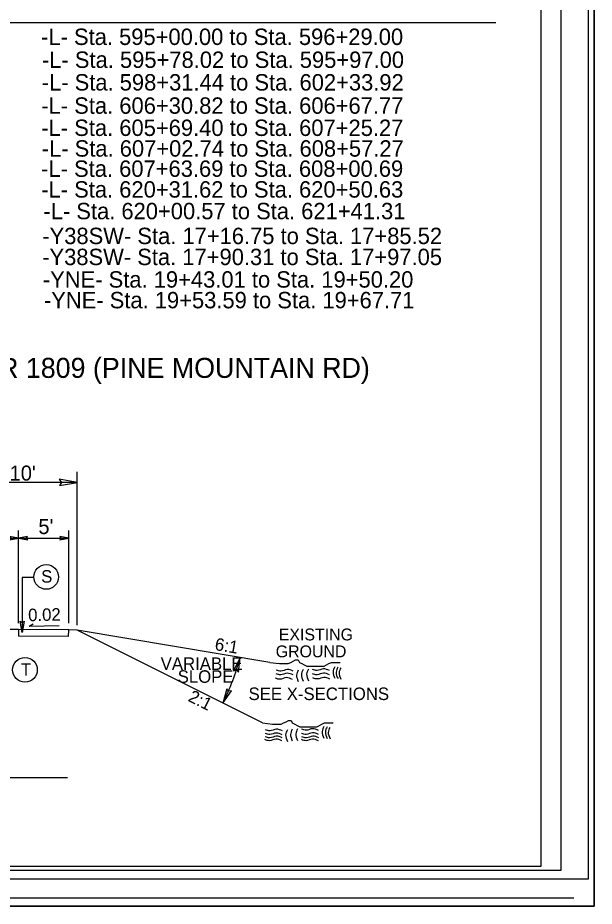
# Model space of a CAD drawing. Extents: x 2294455 to 2294795, y 719276 to 719941.
# Drawn here: x 2294722.6 to 2294794.5, y 719495.3 to 719606.2 of the extents above; entities that cross this region are included whole.
import ezdxf

# ---------------------------------------------------------------- set-up
doc = ezdxf.new("R2010")
doc.units = 0
for name, color, linetype in [('Default', 7, 'Continuous'), ('Old_Level_1', 7, 'Continuous'), ('Old_Level_11', 7, 'Continuous'), ('Old_Level_2', 7, 'Continuous'), ('Old_Level_3', 7, 'Continuous'), ('Sheet Cutting Line CELL', 7, 'Continuous'), ('Sheet Plot Border Inside CELL', 7, 'Continuous'), ('Sheet Plot Border Outside CELL', 7, 'Continuous'), ('Sheet Typical CELL', 7, 'Continuous'), ('Typical Hinge Slope Arterial CELL', 7, 'Continuous'), ('Typical ID Circle CELL', 7, 'Continuous'), ('Typical Terminator CELL', 7, 'Continuous'), ('Typical Text ID Circle CELL', 7, 'Continuous')]:
    doc.layers.add(name, color=color, linetype=linetype)

msp = doc.modelspace()

# ---------------------------------------------------------------- linework, layer by layer
at = {"layer": 'Default'}
msp.add_lwpolyline([(2294454.52, 719715.33), (2294794.52, 719715.33), (2294794.52, 719495.33), (2294454.52, 719495.33)], close=True, dxfattribs=at)
at = {"layer": 'Old_Level_1'}
for p, q in [((2294724.02, 719530.26), (2294724.53, 719530.57)), ((2294724.02, 719530.26), (2294727.79, 719530.34)), ((2294722.72, 719529.84), (2294717.54, 719529.88)), ((2294722.72, 719529.84), (2294722.71, 719529.01)), ((2294728.97, 719529.8), (2294722.72, 719529.84)), ((2294728.94, 719528.97), (2294728.97, 719529.8)), ((2294730.03, 719529.75), (2294728.97, 719529.8)), ((2294753.16, 719518.19), (2294730.03, 719529.75)), ((2294728.94, 719528.97), (2294722.71, 719529.01))]:
    msp.add_line(p, q, dxfattribs=at)
at = {"layer": 'Old_Level_11'}
for p, q in [((2294720.71, 719605.56), (2294782.24, 719605.56)), ((2294730.03, 719530.41), (2294730.03, 719549.52)), ((2294730.05, 719548.21), (2294714.42, 719548.21)), ((2294722.72, 719530.63), (2294722.72, 719542.19)), ((2294728.97, 719530.63), (2294728.97, 719542.19)), ((2294716.92, 719541.25), (2294728.97, 719541.25)), ((2294728.83, 719511.36), (2294666.82, 719511.36))]:
    msp.add_line(p, q, dxfattribs=at)
for points in [[(2294727.8, 719547.83), (2294730.05, 719548.21), (2294727.78, 719548.61), (2294728.07, 719548.21)], [(2294721.59, 719541.05), (2294722.72, 719541.25), (2294721.58, 719541.45), (2294721.73, 719541.25)], [(2294723.84, 719541.44), (2294722.72, 719541.25), (2294723.85, 719541.05), (2294723.7, 719541.25)], [(2294727.84, 719541.05), (2294728.97, 719541.25), (2294727.84, 719541.45), (2294727.98, 719541.25)], [(2294750.14, 719524.51), (2294750.34, 719526.37), (2294749.51, 719524.68), (2294749.89, 719524.82)], [(2294748.7, 719522.47), (2294748.21, 719520.67), (2294749.29, 719522.21), (2294748.89, 719522.14)]]:
    msp.add_lwpolyline(points, close=True, dxfattribs=at)
at = {"layer": 'Old_Level_2'}
for points in [[(2294756.98, 719524.65), (2294756.22, 719524.86), (2294755.43, 719524.66), (2294754.86, 719524.79)], [(2294756.98, 719524.65), (2294756.22, 719524.86), (2294755.43, 719524.66), (2294754.86, 719524.79)], [(2294757.6, 719524.79), (2294757.39, 719524.17), (2294757.61, 719523.35)], [(2294758.2, 719524.85), (2294757.99, 719524.22), (2294758.22, 719523.4)], [(2294758.2, 719524.85), (2294757.99, 719524.22), (2294758.22, 719523.4)], [(2294758.86, 719524.9), (2294758.65, 719524.28), (2294758.87, 719523.45)], [(2294758.86, 719524.9), (2294758.65, 719524.28), (2294758.87, 719523.45)], [(2294761.49, 719524.72), (2294760.74, 719524.94), (2294759.94, 719524.73), (2294759.37, 719524.86)], [(2294761.49, 719524.72), (2294760.74, 719524.94), (2294759.94, 719524.73), (2294759.37, 719524.86)], [(2294762.15, 719525.2), (2294761.94, 719524.58), (2294762.17, 719523.76)], [(2294762.15, 719525.2), (2294761.94, 719524.58), (2294762.17, 719523.76)], [(2294762.54, 719525.16), (2294762.33, 719524.54), (2294762.56, 719523.72)], [(2294762.54, 719525.16), (2294762.33, 719524.54), (2294762.56, 719523.72)], [(2294762.91, 719525.09), (2294762.7, 719524.47), (2294762.92, 719523.65)], [(2294762.91, 719525.09), (2294762.7, 719524.47), (2294762.92, 719523.65)], [(2294756.88, 719523.63), (2294756.13, 719523.85), (2294755.33, 719523.64), (2294754.76, 719523.77)], [(2294756.88, 719523.63), (2294756.13, 719523.85), (2294755.33, 719523.64), (2294754.76, 719523.77)], [(2294756.96, 719524.18), (2294756.2, 719524.39), (2294755.41, 719524.19), (2294754.84, 719524.32)], [(2294756.96, 719524.18), (2294756.2, 719524.39), (2294755.41, 719524.19), (2294754.84, 719524.32)], [(2294761.49, 719524.2), (2294760.74, 719524.41), (2294759.95, 719524.21), (2294759.38, 719524.34)], [(2294761.49, 719524.2), (2294760.74, 719524.41), (2294759.95, 719524.21), (2294759.38, 719524.34)], [(2294761.55, 719523.67), (2294760.8, 719523.88), (2294760, 719523.68), (2294759.43, 719523.81)], [(2294761.55, 719523.67), (2294760.8, 719523.88), (2294760, 719523.68), (2294759.43, 719523.81)], [(2294755.62, 719517.2), (2294754.87, 719517.41), (2294754.08, 719517.21), (2294753.5, 719517.34)], [(2294756.24, 719517.34), (2294756.03, 719516.72), (2294756.26, 719515.9)], [(2294756.24, 719517.34), (2294756.03, 719516.72), (2294756.26, 719515.9)], [(2294756.85, 719517.4), (2294756.64, 719516.77), (2294756.86, 719515.95)], [(2294756.85, 719517.4), (2294756.64, 719516.77), (2294756.86, 719515.95)], [(2294757.5, 719517.45), (2294757.3, 719516.83), (2294757.52, 719516)], [(2294757.5, 719517.45), (2294757.3, 719516.83), (2294757.52, 719516)], [(2294760.13, 719517.27), (2294759.38, 719517.48), (2294758.59, 719517.28), (2294758.02, 719517.41)], [(2294760.13, 719517.27), (2294759.38, 719517.48), (2294758.59, 719517.28), (2294758.02, 719517.41)], [(2294760.8, 719517.75), (2294760.58, 719517.13), (2294760.81, 719516.31)], [(2294761.19, 719517.71), (2294760.98, 719517.09), (2294761.21, 719516.27)], [(2294761.55, 719517.64), (2294761.34, 719517.02), (2294761.57, 719516.2)], [(2294755.56, 719515.97), (2294754.81, 719516.18), (2294754.01, 719515.98), (2294753.44, 719516.11)], [(2294755.6, 719516.73), (2294754.85, 719516.94), (2294754.06, 719516.74), (2294753.48, 719516.87)], [(2294755.6, 719516.73), (2294754.85, 719516.94), (2294754.06, 719516.74), (2294753.48, 719516.87)], [(2294755.6, 719516.33), (2294754.85, 719516.54), (2294754.05, 719516.34), (2294753.48, 719516.47)], [(2294755.6, 719516.33), (2294754.85, 719516.54), (2294754.05, 719516.34), (2294753.48, 719516.47)], [(2294760.12, 719515.97), (2294759.37, 719516.18), (2294758.57, 719515.98), (2294758, 719516.11)], [(2294760.14, 719516.75), (2294759.38, 719516.96), (2294758.59, 719516.76), (2294758.02, 719516.88)], [(2294760.14, 719516.75), (2294759.38, 719516.96), (2294758.59, 719516.76), (2294758.02, 719516.88)], [(2294760.16, 719516.33), (2294759.41, 719516.54), (2294758.62, 719516.34), (2294758.04, 719516.47)], [(2294760.16, 719516.33), (2294759.41, 719516.54), (2294758.62, 719516.34), (2294758.04, 719516.47)]]:
    msp.add_spline(points, degree=3, dxfattribs=at)
at = {"layer": 'Sheet Cutting Line CELL'}
msp.add_line((2294791.96, 719496.34), (2294455.16, 719496.34), dxfattribs=at)
at = {"layer": 'Sheet Plot Border Inside CELL'}
msp.add_lwpolyline([(2294790.42, 719710.84), (2294457.12, 719710.84), (2294457.12, 719499.82), (2294790.42, 719499.82)], close=True, dxfattribs=at)
at = {"layer": 'Sheet Plot Border Outside CELL'}
for points in [[(2294793.79, 719718.76), (2294456.99, 719718.76), (2294456.99, 719498.76), (2294793.79, 719498.76)], [(2294794.52, 719715.33), (2294454.52, 719715.33), (2294454.52, 719495.33), (2294794.52, 719495.33)]]:
    msp.add_lwpolyline(points, close=True, dxfattribs=at)
at = {"layer": 'Sheet Typical CELL'}
msp.add_lwpolyline([(2294787.92, 719710.33), (2294487.92, 719710.33), (2294487.92, 719500.33), (2294787.92, 719500.33)], close=True, dxfattribs=at)
at = {"layer": 'Typical Hinge Slope Arterial CELL'}
msp.add_line((2294754.04, 719525.75), (2294730.03, 719529.75), dxfattribs=at)
for points in [[(2294754.04, 719525.75), (2294755.27, 719525.6), (2294755.58, 719525.6), (2294756.04, 719525.6), (2294756.35, 719525.6), (2294756.66, 719525.75), (2294756.97, 719525.91), (2294757.27, 719526.06), (2294757.58, 719526.06), (2294757.74, 719525.75), (2294758.05, 719525.6), (2294758.35, 719525.44), (2294758.66, 719525.29), (2294758.97, 719525.29), (2294759.28, 719525.29), (2294759.59, 719525.29), (2294759.89, 719525.29), (2294760.2, 719525.29), (2294760.51, 719525.29), (2294760.82, 719525.29), (2294761.12, 719525.44), (2294761.43, 719525.6), (2294761.74, 719525.75), (2294762.2, 719525.75), (2294762.51, 719525.75), (2294762.82, 719525.75)], [(2294753.16, 719518.19), (2294754.39, 719518.04), (2294754.7, 719518.04), (2294755.16, 719518.04), (2294755.47, 719518.04), (2294755.78, 719518.19), (2294756.08, 719518.34), (2294756.39, 719518.5), (2294756.7, 719518.5), (2294756.86, 719518.19), (2294757.16, 719518.04), (2294757.47, 719517.88), (2294757.78, 719517.73), (2294758.09, 719517.73), (2294758.4, 719517.73), (2294758.7, 719517.73), (2294759.01, 719517.73), (2294759.32, 719517.73), (2294759.63, 719517.73), (2294759.93, 719517.73), (2294760.24, 719517.88), (2294760.55, 719518.04), (2294760.86, 719518.19), (2294761.32, 719518.19), (2294761.63, 719518.19), (2294761.94, 719518.19)]]:
    msp.add_lwpolyline(points, dxfattribs=at)
msp.add_arc((2294722.32, 719533.62), 28.94, 333.4349, 345.5, dxfattribs=at)
at = {"layer": 'Typical ID Circle CELL'}
for p, q in [((2294723.16, 719536.33), (2294723.16, 719529.47)), ((2294724.61, 719536.33), (2294723.16, 719536.33))]:
    msp.add_line(p, q, dxfattribs=at)
for centre in [(2294726.16, 719536.41), (2294723.51, 719524.82)]:
    msp.add_circle(centre, 1.54, dxfattribs=at)
at = {"layer": 'Typical Terminator CELL'}
msp.add_lwpolyline([(2294723.4, 719530.9), (2294723.16, 719529.47), (2294722.9, 719530.91), (2294723.16, 719530.72)], close=True, dxfattribs=at)

# ---------------------------------------------------------------- texts
at = {"layer": 'Old_Level_1'}
for s, height, rotation, p in [('-L- Sta. 595+00.00 to Sta. 596+29.00', 2.0454, 0, (2294725.52, 719602.77)), ('-L- Sta. 595+78.02 to Sta. 595+97.00 ', 2.0454, 0, (2294725.63, 719599.91)), ('-L- Sta. 598+31.44 to Sta. 602+33.92 ', 2.0454, 0, (2294725.6, 719597.09)), ('-L- Sta. 606+30.82 to Sta. 606+67.77', 2.0454, 0, (2294725.55, 719594.19)), ('-L- Sta. 605+69.40 to Sta. 607+25.27', 2.0454, 0, (2294725.55, 719591.42)), ('-L- Sta. 607+02.74 to Sta. 608+57.27', 2.0454, 0, (2294725.6, 719588.84)), ('-L- Sta. 607+63.69 to Sta. 608+00.69', 2.0454, 0, (2294725.53, 719586.32)), ('-L- Sta. 620+31.62 to Sta. 620+50.63', 2.0454, 0, (2294725.54, 719583.73)), ('-L- Sta. 620+00.57 to Sta. 621+41.31', 2.0454, 0, (2294725.81, 719581.03)), ('-Y38SW- Sta. 17+16.75 to Sta. 17+85.52', 2.0454, 0, (2294725.67, 719577.93)), ('-Y38SW- Sta. 17+90.31 to Sta. 17+97.05', 2.0454, 0, (2294725.66, 719575.31)), ('-YNE- Sta. 19+43.01 to Sta. 19+50.20', 2.0454, 0, (2294725.74, 719572.5)), ('-YNE- Sta. 19+53.59 to Sta. 19+67.71', 2.0454, 0, (2294725.87, 719569.92)), ('EXISTING', 1.484, 0, (2294755.17, 719528.49)), ('6:1', 1.562, 350.5377, (2294747.11, 719527.3)), ('GROUND', 1.484, 0, (2294754.79, 719526.38)), ('SEE X-SECTIONS', 1.5625, 0, (2294751.4, 719521.05)), ('2:1', 1.562, 333.4349, (2294743.75, 719520.98))]:
    msp.add_text(s, height=height, rotation=rotation, dxfattribs=at).set_placement(p)
at = {"layer": 'Old_Level_11'}
for s, p in [("10'", (2294721.59, 719548.43)), ("5'", (2294725.18, 719541.76))]:
    msp.add_text(s, height=1.875, dxfattribs=at).set_placement(p)
at = {"layer": 'Old_Level_3'}
for s, height, rotation, p in [('-Y38SW- SR 1809 (PINE MOUNTAIN RD)', 2.5, 360, (2294703.56, 719561.24)), ('0.02', 1.562, 1.1457, (2294723.92, 719530.88))]:
    msp.add_text(s, height=height, rotation=rotation, dxfattribs=at).set_placement(p)
at = {"layer": 'Typical Hinge Slope Arterial CELL'}
for s, p in [('VARIABLE ', (2294740.44, 719524.81)), ('SLOPE', (2294742.56, 719523.2))]:
    msp.add_text(s, height=1.562, dxfattribs=at).set_placement(p)
at = {"layer": 'Typical Text ID Circle CELL'}
for s, p in [('S', (2294725.53, 719535.7)), ('T', (2294723, 719524.08))]:
    msp.add_text(s, height=1.56, dxfattribs=at).set_placement(p)

doc.saveas('drawing.dxf')
